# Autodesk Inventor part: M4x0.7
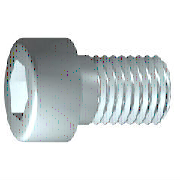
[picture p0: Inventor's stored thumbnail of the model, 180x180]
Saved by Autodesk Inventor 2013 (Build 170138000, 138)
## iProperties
IsCustomPart: 1
Created: 2009-02
Part Number: M4x0.7
Material: 강철, 연강
Description: 6각머리 태핑 나사
Document SubType Name: Modeling
Standard: KS B 1003
Designer: SeoGD™[esajin.kr]
Standards Organization: KS
Language: ko-KR
Size Designation: M 4 x 16
Categories: <MemberInstance><Categories><Category DisplayName="조임쇠" InternalName="e4da775c-781d-43d5-af7c-5136215cf5a6" Mnemonic="FSTN"><Category DisplayName="볼트" InternalN
Density: 7.86 g/cm^3
Mass: 2.62973 g
Surface Area: 3.81118 cm^2
Volume: 0.334572 cm^3
Author: SeoGD™[esajin.kr]
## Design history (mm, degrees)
sketch "스케치1"
  geometry: L1 (-1, 0)-(16, 0); L2 (16, 0)-(16, 2); L3 (16, 2)-(1.75, 2); L4 (1.75, 2)-(1.32, 2); L5 (1.32, 2)-(0, 2); L6 (0, 2)-(0, 3.5); L7 (0, 3.5)-(-4, 3.5); L8 (-4, 3.5)-(-4, 1.732); L9 (-4, 1.732)-(-2, 1.732); L10 (-2, 1.732)-(-1, 0); L11 (-8, 0)-(20, 0) reference; L12 (0, -0.7)-(0, 4.2) reference; L13 (1.75, 2)-(0, 2)
  constraints: 22 end point, 6 parallel, 2 collinear, 2 perpendicular, 1 horizontal, 1 point on line
  dimensions: "d1" = 14.25 distance from line of L3.end L2 (= GEL); "d2" = 0.42952 distance of L4.end L3.end (computed from GAL); "d3" = 4 distance between parallel lines of L8 L6 (= KOH); "d4" = 2 distance of L8.end L9.end (= INTI); "d5" = 60 deg angle of L10 L1; "d6" = 4 diameter of L3 L1 (= GD); "d7" = 4 diameter of L5 L1 (= BDM); "d8" = 3.4641 diameter of L9 L1 (= 1.1547 x SW); "d9" = 7 diameter of L7 L1 (= KOD); "d26" = 16 distance between parallel lines of L12 L2 (= NLG)
revolve "본체" sketch "스케치1" stored, may be unused: angle "d10" = 90 deg
sketch "스케치2"
  geometry: L1 (0, -4.9)-(0, 4.9) reference; L2 (-4.9, 0)-(4.9, 0) reference; L3 (1.732, 0)-(0.866, -1.5); L4 (0.866, -1.5)-(-0.866, -1.5); L5 (-0.866, -1.5)-(-1.732, 0); L6 (-1.732, 0)-(-0.866, 1.5); L7 (-0.866, 1.5)-(0.866, 1.5); L8 (0.866, 1.5)-(1.732, 0); 2 further points
  constraints: 12 end point, 1 coincident, 1 horizontal alignment, 1 point on line, 12 other
extrude "슬롯" join sketch "스케치2" stored distance "d11" = 10; taper "d12" = 0 deg
workplane "Work Plane1"
fillet "Fillet2" dims "d30" = 0.1 (= R)
body "Solid1"
fillet "모깎기1" dims "d17" = 0.4 (= RR)
feature "스레드" dims "d13" = 14.25 (= GEL), "d14" = 0
chamfer "모따기1" distance "d15" = 0.42941 (= -0.5 x SPD + 0.5 x GD); stored, may be unused: second distance "d16" = 0.42941 (= GUL), angle "d27" = 45 deg
other parameters: "GD" = 4 (= NND) [user parameter; used in 2 equation terms], "NLG" = 16 [user parameter; used in 1 equation term], "GEL" = 14.25 [user parameter; used in 2 equation terms], "KOD" = 7 [user parameter; used in 1 equation term], "KOH" = 4 [user parameter; used in 1 equation term], "INTI" = 2 [user parameter; used in 1 equation term], "GAL" = 0.42941 (= 0.61345 x PTC) [user parameter; used in 1 equation term], "GUL" = 0.42941 (= 0.61345 x PTC) [user parameter; used in 1 equation term], "BDM" = 4 (= NND) [user parameter; used in 1 equation term], "SW" = 3 [user parameter; used in 2 equation terms], "RR" = 0.4 [user parameter; used in 1 equation term], "SPD" = 3.14117 (= NND - 1.2269 x PTC) [user parameter; used in 1 equation term], "d19" = 0, "d28" = 0, "d29" = 0, "R" = 0.1 [user parameter; used in 1 equation term], "PHH" = 0.2 [user parameter], "GD1" = 3.14117 (= THREADDIA - 1.2269 x PTC) [user parameter], "THREADDIA" = 4 [user parameter; used in 1 equation term], "FAWI" = 45 deg [user parameter], "TPU" = 14.28571 (computed from PTC) [user parameter], "PTC" = 0.7 [user parameter; used in 5 equation terms], "NND" = 4 [user parameter; used in 3 equation terms], "TOA" = 30 deg [user parameter], "E0" = 3.465 (= 1.155 x SW) [user parameter]
